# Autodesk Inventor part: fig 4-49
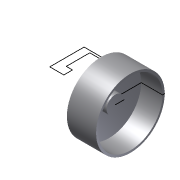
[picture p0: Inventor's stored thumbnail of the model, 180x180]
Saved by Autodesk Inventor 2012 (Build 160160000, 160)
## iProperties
Created: 2004-05
Part Number: fig 4-49
Document SubType Name: Modeling
Designer: CADCIM Technologies
Manufacturer: Standard
Standards Organization: Custom
Density: 1 g/cm^3
Material: Default
Author: CADCIM Technologies
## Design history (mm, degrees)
sketch "Sketch1"
  geometry: L1 (37.08, 12.209)-(23.643, 12.209); L2 (23.643, 12.209)-(23.643, 45.026); L3 (23.643, 45.026)-(51.55, 45.026); L4 (51.55, 45.026)-(51.55, 42.959); L5 (51.55, 42.959)-(31.137, 42.959); L6 (31.137, 42.959)-(31.137, 20.478); L7 (31.137, 20.478)-(37.08, 20.478); L8 (37.08, 20.478)-(37.08, 12.209); L9 (86.437, 12.209)-(73, 12.209); L10 (73, 12.209)-(73, 45.026); L11 (73, 45.026)-(100.907, 45.026); L12 (100.907, 45.026)-(100.907, 42.959); L13 (100.907, 42.959)-(80.494, 42.959); L14 (80.494, 42.959)-(80.494, 20.478); L15 (80.494, 20.478)-(86.437, 20.478); L16 (86.437, 20.478)-(86.437, 12.209)
  constraints: 32 end point, 12 parallel, 2 horizontal, 2 perpendicular
revolve "Revolution1" sketch "Sketch1" stored, may be unused: angle "d0" = 90 deg
body "Solid1"
